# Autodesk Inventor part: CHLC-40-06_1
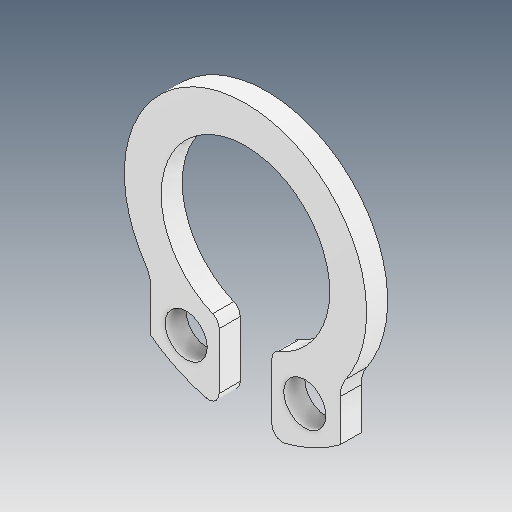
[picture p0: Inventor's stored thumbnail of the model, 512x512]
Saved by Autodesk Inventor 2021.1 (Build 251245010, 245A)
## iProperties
Created: 2021-05
Part Number: CHLC-40-06_1
Material: Ogólny
Document SubType Name: Modeling
Designer: user
Density: 1 g/cm^3
Appearance: Domyślna
Author: user
Revision Number: ÈÎºÎ
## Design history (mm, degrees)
feature "ÊäÈë1"
node "Bryła1"
